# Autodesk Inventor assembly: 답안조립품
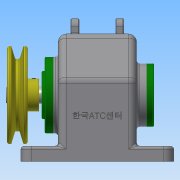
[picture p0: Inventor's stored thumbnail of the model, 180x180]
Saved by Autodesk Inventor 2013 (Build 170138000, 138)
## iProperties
Created: 2016-12
Part Number: 답안조립품
Document SubType Name: Assembly
Designer: Administrator
Author: Administrator
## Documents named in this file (15)
- C:\Users\Administrator\Desktop\461208V1023\답안조립품.iam
- C:\Users\Administrator\Desktop\461208V1023\V-벨트풀리.ipt
- C:\Users\Administrator\Desktop\461208V1023\뒤커버.ipt
- C:\Users\Administrator\Desktop\461208V1023\멈춤나사 - M4x10.ipt
- C:\Users\Administrator\Desktop\461208V1023\베어링 6203.ipt
- C:\Users\Administrator\Desktop\461208V1023\본체.ipt
- C:\Users\Administrator\Desktop\461208V1023\볼트 M3 x 8.ipt
- C:\Users\Administrator\Desktop\461208V1023\볼트 M3 x 10.ipt
- C:\Users\Administrator\Desktop\461208V1023\부시.ipt
- C:\Users\Administrator\Desktop\461208V1023\스퍼기어.ipt
- C:\Users\Administrator\Desktop\461208V1023\앞커버.ipt
- C:\Users\Administrator\Desktop\461208V1023\오일씰 28 40 8.ipt
- C:\Users\Administrator\Desktop\461208V1023\축.ipt
- C:\Users\Administrator\Desktop\461208V1023\키 - 5 x 5 x 18.ipt
- C:\Users\Administrator\Desktop\461208V1023\키 - 6 x 6 x 22.ipt
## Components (9 placed, 3 different names)
1. V-벨트풀리:1
2. ISO 4762 M3 x 8:1
3. ISO 4762 M3 x 8:2
4. ISO 4762 M3 x 8:3
5. ISO 4762 M3 x 8:4
6. ISO 4762 M3 x 10:1
7. ISO 4762 M3 x 10:2
8. ISO 4762 M3 x 10:3
9. ISO 4762 M3 x 10:4
